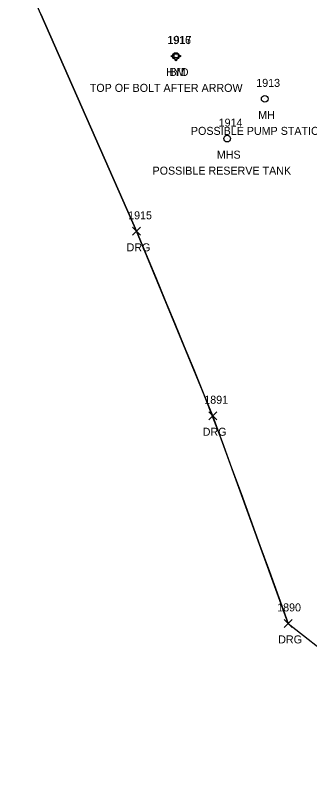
# Model space of a CAD drawing. Extents: x 1623612 to 1625808, y 621345 to 627748.
# Drawn here: x 1624398.7 to 1624472.4, y 626346.5 to 626535.9 of the extents above; entities that cross this region are included whole.
import ezdxf

# ---------------------------------------------------------------- set-up
doc = ezdxf.new("R2010")
doc.units = 0
for name, color, linetype in [('C_A', 7, 'Continuous'), ('C_C', 7, 'Continuous'), ('C_I', 7, 'Continuous'), ('CPBM', 7, 'Continuous'), ('LSOGP', 7, 'Continuous'), ('R_A', 7, 'Continuous'), ('R_I', 7, 'Continuous'), ('R_TIC', 7, 'Continuous'), ('RDG', 7, 'Continuous'), ('U_A', 7, 'Continuous'), ('U_C', 7, 'Continuous'), ('U_I', 7, 'Continuous'), ('USMH', 7, 'Continuous'), ('UUMH', 7, 'Continuous'), ('UWFH', 7, 'Continuous')]:
    doc.layers.add(name, color=color, linetype=linetype)

msp = doc.modelspace()

# ---------------------------------------------------------------- linework, layer by layer
at = {"layer": 'CPBM'}
for p, q in [((1624438.46, 626525.22), (1624438.46, 626526.22)), ((1624438.46, 626526.22), (1624439.46, 626526.22)), ((1624438.96, 626525.72), (1624438.96, 626525.72)), ((1624438.96, 626525.72), (1624438.96, 626525.72)), ((1624439.46, 626526.22), (1624439.46, 626525.22)), ((1624439.46, 626525.22), (1624438.46, 626525.22))]:
    msp.add_line(p, q, dxfattribs=at)
at = {"layer": 'LSOGP'}
msp.add_lwpolyline([(1624405.11, 626536.18), (1624408.54, 626528.42), (1624411.96, 626520.66), (1624415.38, 626512.9), (1624418.81, 626505.14), (1624422.23, 626497.38), (1624425.65, 626489.62), (1624429.07, 626481.86), (1624431.45, 626476.1), (1624433.83, 626470.33), (1624436.21, 626464.57), (1624438.59, 626458.81), (1624440.97, 626453.05), (1624443.35, 626447.29), (1624445.73, 626441.52), (1624450.46, 626429.27), (1624452.82, 626422.78), (1624455.18, 626416.3), (1624457.54, 626409.81), (1624459.9, 626403.32), (1624462.26, 626396.83), (1624464.62, 626390.34), (1624466.98, 626383.85), (1624514.57, 626346.5)], dxfattribs=at)
at = {"layer": 'R_TIC'}
for points in [[(1624428.07, 626480.86), (1624430.07, 626482.86)], [(1624430.07, 626480.86), (1624428.07, 626482.86)], [(1624447.1, 626434.76), (1624449.1, 626436.76)], [(1624449.1, 626434.76), (1624447.1, 626436.76)], [(1624465.98, 626382.85), (1624467.98, 626384.85)], [(1624467.98, 626382.85), (1624465.98, 626384.85)]]:
    msp.add_lwpolyline(points, dxfattribs=at)
at = {"layer": 'RDG'}
msp.add_lwpolyline([(1624466.98, 626383.85), (1624448.1, 626435.76), (1624429.07, 626481.86), (1624401.69, 626543.94), (1624398.7, 626570.07), (1624407.46, 626593.01), (1624423.09, 626615.87), (1624430.36, 626619.32), (1624433.64, 626619.4)], dxfattribs=at)
at = {"layer": 'USMH'}
for p, q in [((1624451.7, 626505.03), (1624451.7, 626505.03)), ((1624452.53, 626505.03), (1624452.53, 626505.03))]:
    msp.add_line(p, q, dxfattribs=at)
msp.add_circle((1624451.7, 626505.03), 0.833, dxfattribs=at)
at = {"layer": 'UUMH'}
for p, q in [((1624461.09, 626514.97), (1624461.09, 626514.97)), ((1624461.93, 626514.97), (1624461.93, 626514.97))]:
    msp.add_line(p, q, dxfattribs=at)
msp.add_circle((1624461.09, 626514.97), 0.833, dxfattribs=at)
at = {"layer": 'UWFH'}
msp.add_line((1624438.88, 626525.67), (1624438.88, 626525.67), dxfattribs=at)
for centre, radius in [((1624437.88, 626525.67), 0.167), ((1624438.88, 626525.67), 0.833), ((1624439.88, 626525.67), 0.167), ((1624438.88, 626524.67), 0.167)]:
    msp.add_circle(centre, radius, dxfattribs=at)

# ---------------------------------------------------------------- texts
at = {"layer": 'C_A'}
msp.add_text('BM', height=2, dxfattribs=at).set_placement((1624437.28, 626520.72))
at = {"layer": 'C_C'}
msp.add_text('TOP OF BOLT AFTER ARROW', height=2, dxfattribs=at).set_placement((1624417.36, 626516.72))
at = {"layer": 'C_I'}
msp.add_text('1917', height=2, dxfattribs=at).set_placement((1624436.84, 626528.72))
at = {"layer": 'R_A'}
for p in [(1624426.56, 626476.86), (1624445.59, 626430.76), (1624464.46, 626378.85)]:
    msp.add_text('DRG', height=2, dxfattribs=at).set_placement(p)
at = {"layer": 'R_I'}
for s, p in [('1915', (1624426.95, 626484.86)), ('1891', (1624445.98, 626438.76)), ('1890', (1624464.2, 626386.85))]:
    msp.add_text(s, height=2, dxfattribs=at).set_placement(p)
at = {"layer": 'U_A'}
for s, p in [('HYD', (1624436.4, 626520.67)), ('MH', (1624459.45, 626509.97)), ('MHS', (1624449.11, 626500.03))]:
    msp.add_text(s, height=2, dxfattribs=at).set_placement(p)
at = {"layer": 'U_C'}
for s, p in [('POSSIBLE PUMP STATION', (1624442.64, 626505.97)), ('POSSIBLE RESERVE TANK', (1624433.05, 626496.03))]:
    msp.add_text(s, height=2, dxfattribs=at).set_placement(p)
at = {"layer": 'U_I'}
for s, p in [('1916', (1624436.7, 626528.67)), ('1913', (1624458.97, 626517.97)), ('1914', (1624449.57, 626508.03))]:
    msp.add_text(s, height=2, dxfattribs=at).set_placement(p)

doc.saveas('drawing.dxf')
